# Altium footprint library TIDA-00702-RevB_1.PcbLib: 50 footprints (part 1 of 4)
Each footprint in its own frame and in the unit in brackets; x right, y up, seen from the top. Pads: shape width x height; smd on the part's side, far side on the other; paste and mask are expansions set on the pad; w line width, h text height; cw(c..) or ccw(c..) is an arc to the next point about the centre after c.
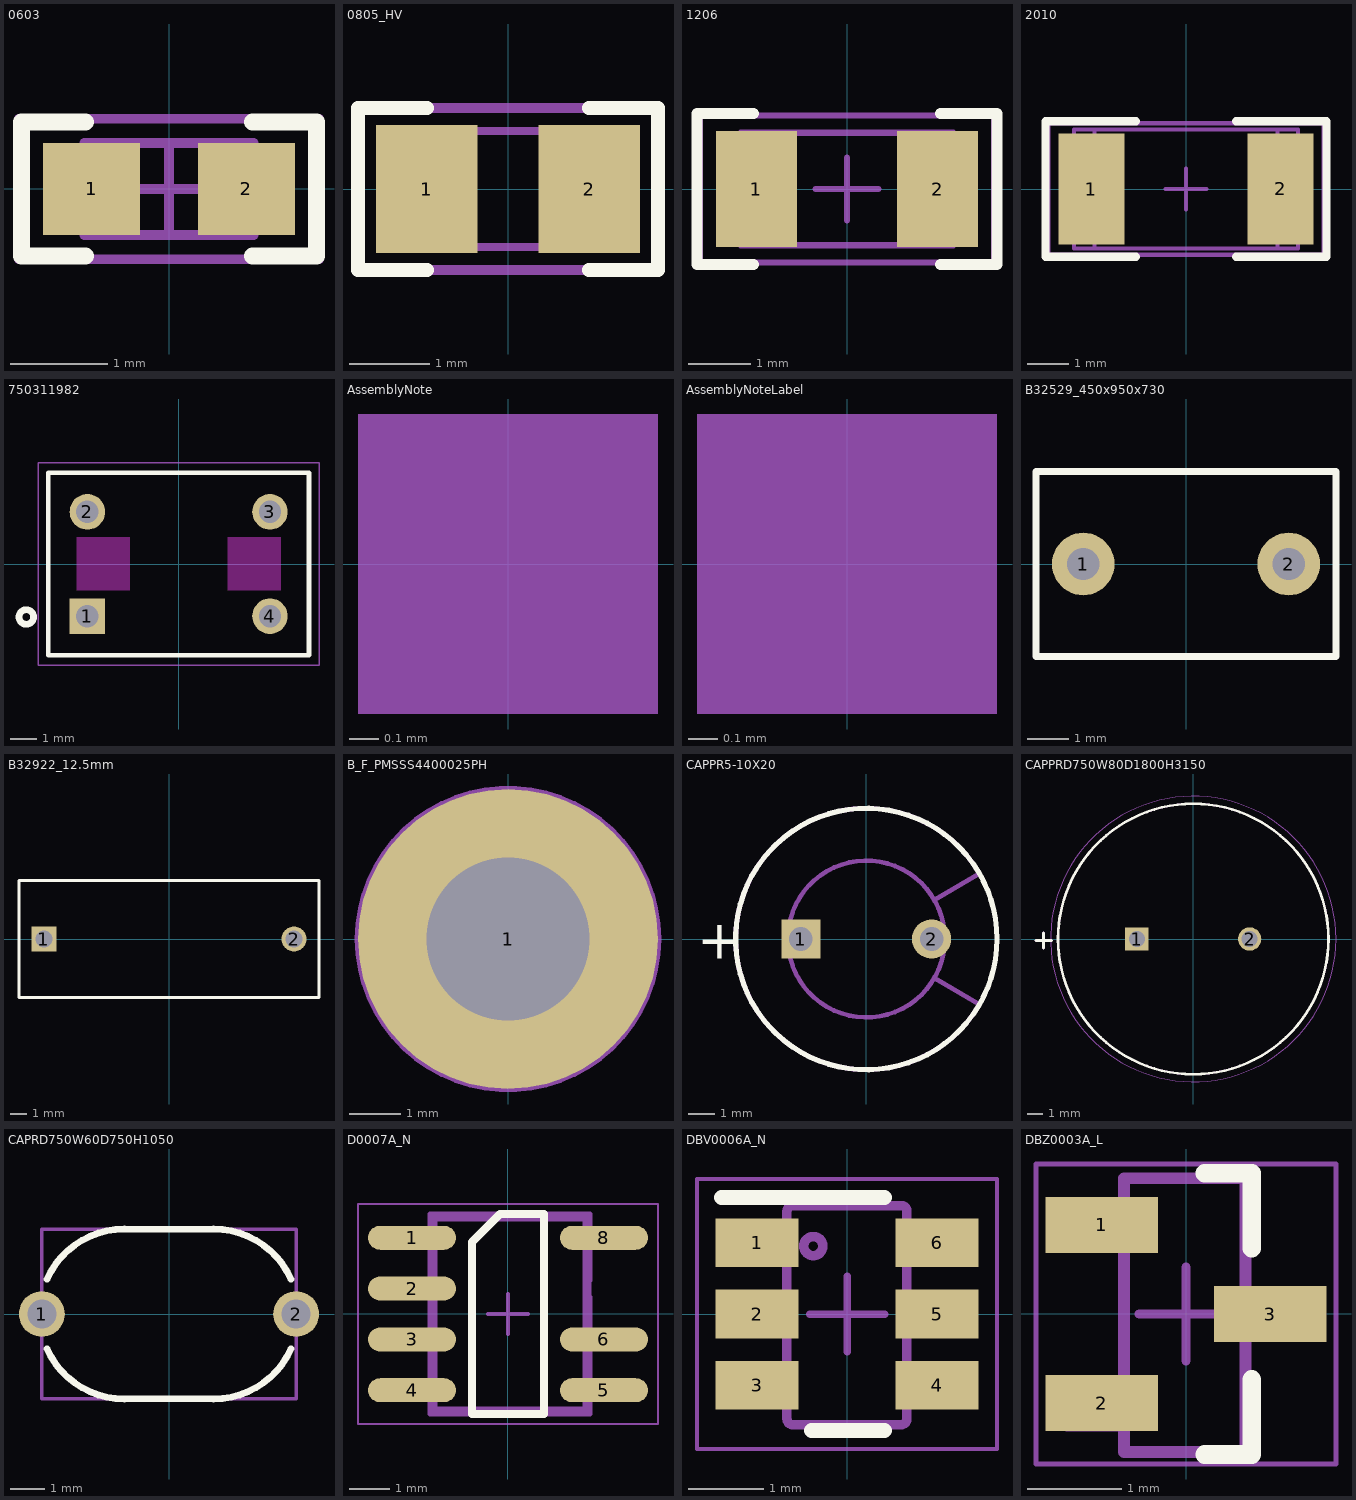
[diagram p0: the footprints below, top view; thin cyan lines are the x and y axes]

## 0603 [mm] "0603 from SM-752 data"
height 0.85
pads (2):
  rect 1x0.95 smd: 1(-0.8,0) 2(0.8,0)
Top Overlay:
  lines w0.178: -0.864,-0.691 -1.524,-0.691 -1.524,0.693 -0.864,0.693 ; 0.864,-0.691 1.524,-0.691 1.524,0.693 0.864,0.693
Mechanical 5:
  lines w0.1: -1.55,-0.725 1.55,-0.725 1.55,0.725 -1.55,0.725 -1.55,-0.725
  text ".Designator" at 1.162,0.431 h0.89
Mechanical 13:
  lines w0.1: -0.55,-0.475 -0.55,0.475 ; 0.55,-0.475 0.55,0.475 ; -0.875,-0.475 -0.875,0.475 0.875,0.475 0.875,-0.475 -0.875,-0.475
Mechanical 15:
  lines w0.1: -0.475,0 0.475,0 ; 0,-0.475 0,0.475 ; -1.55,-0.725 -1.55,0.725 1.55,0.725 1.55,-0.725 -1.55,-0.725
3D body: height 0.85, standoff 0, extent 0.551,-0.474 0.874,0.474
3D body: height 0.85, standoff 0, extent -0.549,-0.474 0.549,0.474
3D body: height 0.85, standoff 0, extent -0.874,-0.474 -0.551,0.474

## 0805_HV [mil] "0805 with 30mil clearance between pads"
height 43.31
pads (2):
  rect 50x63 smd: 1(-40,0) 2(40,0)
Top Overlay:
  lines w7: -40,-40 -74,-40 -74,0 -74,40 -40,40 ; 40,-40 74,-40 74,0 74,40 40,40
Mechanical 5:
  lines w5: -74,-40 -74,40 74,40 74,-40 -74,-40
  text ".Designator" at 37,22 h35
Mechanical 13:
  lines w3.94: -25.59,-28.54 -25.59,28.54 ; 25.59,-28.54 25.59,28.54 ; -43.31,-28.54 43.31,-28.54 43.31,28.54 -43.31,28.54 -43.31,-28.54
3D body: height 43.31, standoff 0, extent -43.29,-28.52 -25.61,28.52
3D body: height 43.31, standoff 0, extent -25.57,-28.52 25.57,28.52
3D body: height 43.31, standoff 0, extent 25.61,-28.52 43.29,28.52

## 1206 [mm] "1206 from SM-752 data"
height 1.35
pads (2):
  rect 1.3x1.85 smd: 1(-1.45,0) 2(1.45,0)
Top Overlay:
  lines w0.178: -1.5,-1.21 -2.4,-1.21 -2.4,1.21 -1.5,1.21 ; 1.5,-1.21 2.4,-1.21 2.4,1.21 1.5,1.21
Mechanical 5:
  lines w0.1: -1.7,-0.9 1.7,-0.9 1.7,0.9 -1.7,0.9 -1.7,-0.9
  text ".Designator" at -1.475,-0.4 h0.89
Mechanical 13:
  lines w0.1: -1.2,-0.9 -1.2,0.9 ; 1.2,-0.9 1.2,0.9 ; -1.7,-0.9 1.7,-0.9 1.7,0.9 -1.7,0.9 -1.7,-0.9
Mechanical 15:
  lines w0.1: -0.5,0 0.5,0 ; 0,-0.5 0,0.5 ; -2.35,-1.175 2.35,-1.175 2.35,1.175 -2.35,1.175 -2.35,-1.175
3D body: height 1.35, standoff 0, extent -1.699,-0.899 -1.201,0.899
3D body: height 1.35, standoff 0, extent -1.199,-0.899 1.199,0.899
3D body: height 1.35, standoff 0, extent 1.201,-0.899 1.699,0.899

## 2010 [mm] "Chip Capacitor, Body 5.08x2.54mm, IPC Medium Density"
height 1.66
pads (2):
  rect 1.6x2.7 smd: 1(-2.3,0) 2(2.3,0)
Top Overlay:
  lines w0.2: -1.219,-1.65 -3.419,-1.65 -3.419,1.65 -1.219,1.65 ; 1.219,-1.65 3.419,-1.65 3.419,1.65 1.219,1.65
Mechanical 5:
  lines w0.1: -2.73,-1.45 -2.73,1.45 2.73,1.45 2.73,-1.45 -2.73,-1.45
  text ".Designator" at -0.787,0.737 h0.89
Mechanical 13:
  lines w0.1: -2.23,-1.45 -2.23,1.45 ; 2.23,-1.45 2.23,1.45 ; -2.73,-1.45 2.73,-1.45 2.73,1.45 -2.73,1.45 -2.73,-1.45
Mechanical 15:
  lines w0.1: -0.5,0 0.5,0 ; 0,-0.5 0,0.5 ; -3.35,-1.6 3.35,-1.6 3.35,1.6 -3.35,1.6 -3.35,-1.6
3D body: height 1.66, standoff 0, extent -2.729,-1.449 -2.231,1.449
3D body: height 1.66, standoff 0, extent -2.229,-1.449 2.229,1.449
3D body: height 1.66, standoff 0, extent 2.231,-1.449 2.729,1.449

## 750311982 [mm] "4 LEAD,TH"
height 6.8
pads (4):
  rect 1.362x1.362 / inner round 1.362 / far side rect 1.362x1.362 hole 0.854: 1(-3.5,-2)
  round 1.362 hole 0.854: 2(-3.5,2) 3(3.5,2) 4(3.5,-2)
Top Layer keep-out:
  rectangle: 1.874,-1.024 3.928,1.03
  rectangle: -3.926,-1.024 -1.872,1.03
Top Overlay:
  circle w0.254: c-5.842,-2.032 r0.279
  lines w0.178: -5,-3.5 -5,3.5 5,3.5 5,-3.5 -5,-3.5
  text ".Designator" at -5.597,-0.279 h0.89
Bottom Overlay:
  lines w0.178: -5,-3.5 -5,-2.5 ; -5,-1.5 -5,-0.5 ; -5,0.5 -5,1.5 ; -5,2.5 -5,3.5 ; -4.572,-3.5 -3.572,-3.5 ; -4.572,3.5 -3.572,3.5 ; -2.572,-3.5 -1.572,-3.5 ; -2.572,3.5 -1.572,3.5 ; -0.572,-3.5 0.428,-3.5 ; -0.572,3.5 0.428,3.5 ; 1.428,-3.5 2.428,-3.5 ; 1.428,3.5 2.428,3.5 ; 3.428,-3.5 4.428,-3.5 ; 3.428,3.5 4.428,3.5 ; 5,-3.5 5,-2.5 ; 5,-1.5 5,-0.5 ; 5,0.5 5,1.5 ; 5,2.5 5,3.5
Mechanical 5:
  lines w0.127: -5,-3.5 5,-3.5 5,3.5 -5,3.5 -5,-3.5
  text ".Designator" at 0.296,-0.737 h0.89
Mechanical 15:
  lines w0.05: -5.381,-3.881 -5.381,3.881 5.381,3.881 5.381,-3.881 -5.381,-3.881
Mechanical 17:
  text "LEAD LENGTH:3 +/- 0.5MM" at -10.795,1.651 h1.02
3D body: height 6.8, standoff 0, extent -5,-3.5 5,3.5

## AssemblyNote [mm] "Assembly Note"
Mechanical 5:
  rectangle: -0.508,-0.508 0.508,0.508
  text ".Designator" at -4.191,-0.508 h0.89
  text ".Comment" at 1.143,-0.508 h0.89

## AssemblyNoteLabel [mm] "Assembly Note for PCB Labels"
Mechanical 5:
  rectangle: -0.508,-0.508 0.508,0.508
  text ".Designator" at -4.191,-0.508 h0.89
  text "Install label in silkscreened box after final wash.  Text shall be 8 pt font.  Text shall be per the Label Table in the PDF schematic." at 1.143,-0.508 h0.89

## B32529_450x950x730 [mil] "EPCOS"
height 374.02
pads (2):
  round 60 hole 31: 1(-98.43,0) 2(98.43,0)
Top Overlay:
  lines w7: -143.7,-88.58 -143.7,88.58 143.7,88.58 143.7,-88.58 -143.7,-88.58
Mechanical 5:
  lines w3.94: -143.7,-88.58 143.7,-88.58 143.7,88.58 -143.7,88.58 -143.7,-88.58
  text ".Designator" at -70.87,-19.68 h35
3D body: height 374.02, standoff 0, extent -143.7,-88.58 143.7,88.58
3D body: height 0, standoff -78.74, extent 88.66,-9.82 108.27,9.82
3D body: height 0, standoff -78.74, extent -108.19,-9.82 -88.58,9.82

## B32922_12.5mm [mm] "Epcos film capacitors, 15mm spacing"
height 12.5
pads (2):
  rect 1.5x1.5 hole 1: 1(-7.5,0)
  round 1.5 hole 1: 2(7.5,0)
Top Overlay:
  lines w0.178: -9,-3.5 -9,0 -9,3.5 0,3.5 9,3.5 9,0 9,-3.5 0,-3.5 -9,-3.5
Mechanical 5:
  lines w0.127: -9,-3.5 0,-3.5 9,-3.5 9,0 9,3.5 0,3.5 -9,3.5 -9,0 -9,-3.5
  text ".Designator" at 0.419,-0.67 h0.89
3D body: height 12.5, standoff 0, extent -8.999,-3.499 8.999,3.499

## B_F_PMSSS4400025PH [mil] "MACHINE SCREW PAN PHILLIPS 4-40"
height 82.68
pads (1):
  round 230 hole 125: 1(0,0)
Mechanical 5:
  circle w5: c0,0 r115
  text ".Designator" at -33,-16 h35
3D body: height 79.21, standoff -248.03, extent -109.49,-109.49 109.51,109.51

## CAPPR5-10X20 [mm] "Capacitor, Electrolytic, Radial; Body 10 x 20 mm (Dia.xH typ); Pin Spacing 5 mm (typ)"
height 22
pads (2):
  rect 1.5x1.5 hole 0.9: 1(-2.5,0)
  round 1.5 hole 0.9: 2(2.5,0)
Top Overlay:
  circle w0.2: c0,0 r5
  text "+" at -6.475,-0.75 h1.5
Mechanical 5:
  text ".Designator" at -0.127,-0.813 h0.89
Mechanical 13:
  circle w0.178: c0,0 r3
  circle w0.178: c-2.5,0 r0.3
  circle w0.178: c2.5,0 r0.3
  lines w0.178: 2.623,-1.5 4.33,-2.5 cw(c0,0) 4.33,2.5 ; 2.623,1.5 4.33,2.5
3D body: height 22, standoff 0, extent 2.597,-2.506 5.011,2.506
3D body: height 22, standoff 0, extent -5.01,-5.01 4.339,5.01
3D body: height 22, standoff 0, extent -3.009,-3.009 3.009,3.009
3D body: height 1, standoff -2.54, extent -2.805,-0.305 -2.195,0.305
3D body: height 1, standoff -2.54, extent 2.195,-0.305 2.805,0.305

## CAPPRD750W80D1800H3150 [mm] "CAPACITOR, POLARIZED, 0.8MM LEAD DIA, PITCH 7.5MM"
height 33
pads (2):
  rect 1.554x1.554 / inner round 1.554 / far side rect 1.554x1.554 hole 1.054: 1(-3.75,0)
  round 1.554 hole 1.054: 2(3.75,0)
Top Overlay:
  circle w0.178: c0,0 r9
  lines w0.2: -10.465,-0.102 -9.449,-0.102 ; -9.957,-0.61 -9.957,0.406
Mechanical 5:
  circle w0.127: c0,0 r9
  lines w0.2: -10.465,-0.102 -9.449,-0.102 ; -9.957,-0.61 -9.957,0.406
  text ".Designator" at 0.305,0.025 h0.89
Mechanical 15:
  circle w0.05: c0,0 r9.5
3D body: height 33, standoff 0, extent -8.929,-8.982 9,8.982

## CAPRD750W60D750H1050 [mm] "Vishay BC Components"
height 10.5
pads (2):
  round 1.35 hole 0.85: 1(-3.75,0) 2(3.75,0)
Top Overlay:
  lines w0.2: -3.6,-1.025 ccw(c-1.316,-0.008) -1.316,-2.508 ; -3.6,1.025 cw(c-1.316,0.008) -1.316,2.508 ; -1.5,-2.5 1.5,-2.5 ; -1.5,2.5 1.5,2.5 ; 1.316,-2.508 ccw(c1.316,-0.008) 3.6,-1.025 ; 1.316,2.508 cw(c1.316,0.008) 3.6,1.025
Mechanical 5:
  lines w0.1: -3.75,-2.5 3.75,-2.5 3.75,2.5 -3.75,2.5 -3.75,-2.5
  text ".Designator" at -0.94,1.245 h0.89
3D body: height 6, standoff -2, extent 3.453,-0.299 4.05,0.3
3D body: height 6, standoff -2, extent -4.047,-0.299 -3.45,0.3
3D body: height 10.49, standoff 3.01, extent -3.72,-2.5 3.75,2.5

## D0007A_N [mm] "SOIC, 7-Leads, Body 4.9x3.9mm, Pitch 1.27mm, IPC Medium Density"
height 1.75
pads (7):
  oval 2.2x0.6 smd: 1(-2.4,1.905) 2(-2.4,0.635) 3(-2.4,-0.635) 4(-2.4,-1.905) 5(2.4,-1.905) 6(2.4,-0.635) 8(2.4,1.905)
Top Overlay:
  lines w0.2: -0.9,-2.5 -0.9,1.8 -0.2,2.5 0.9,2.5 0.9,-2.5 -0.9,-2.5
Mechanical 5:
  lines w0.127: -1.95,-2.11 -1.95,-2.5 ; -1.95,-1.7 -1.95,-0.84 ; -1.95,-0.43 -1.95,0.43 ; -1.95,0.84 -1.95,1.7 ; -1.95,2.11 -1.95,2.5 ; 2.05,-2.11 2.05,-2.5 ; 2.05,-1.7 2.05,-0.84 ; 2.05,-0.43 2.05,0.43 2.03,0.43 2.03,0.84 2.05,0.84 2.05,1.7 ; 2.05,2.11 2.05,2.5 ; -2.325,-2.11 -2.325,-1.7 ; -2.325,-2.11 -2.045,-2.11 -1.931,-2.11 -1.931,-1.7 -2.045,-1.7 -2.325,-1.7 ; -2.325,-2.11 -2.39,-2.11 -2.95,-2.11 -2.95,-1.7 -2.39,-1.7 -2.325,-1.7 ; -2.325,-0.84 -2.325,-0.43 ; -2.325,-0.84 -2.045,-0.84 -1.931,-0.84 -1.931,-0.43 -2.045,-0.43 -2.325,-0.43 ; -2.325,-0.84 -2.39,-0.84 -2.95,-0.84 -2.95,-0.43 -2.39,-0.43 -2.325,-0.43 ; -2.325,0.43 -2.045,0.43 -1.931,0.43 -1.931,0.84 -2.045,0.84 -2.325,0.84 ; -2.325,0.43 -2.39,0.43 -2.95,0.43 -2.95,0.84 -2.39,0.84 -2.325,0.84 ; -2.325,0.43 -2.325,0.84 ; -2.325,1.7 -2.045,1.7 -1.931,1.7 -1.931,2.11 -2.045,2.11 -2.325,2.11 ; -2.325,1.7 -2.325,2.11 ; -2.325,1.7 -2.39,1.7 -2.95,1.7 -2.95,2.11 -2.39,2.11 -2.325,2.11 ; -1.95,-2.5 2.05,-2.5 ; -1.95,-2.5 -1.822,-2.372 ; -1.95,2.5 -1.822,2.372 ; -1.95,2.5 2.05,2.5 ; -1.822,-2.372 -1.822,2.372 ; -1.822,-2.372 1.922,-2.372 ; -1.822,2.372 1.922,2.372 ; 1.922,-2.372 1.922,2.372 ; 1.922,-2.372 2.05,-2.5 ; 1.922,2.372 2.05,2.5 ; 2.425,-2.11 2.49,-2.11 3.05,-2.11 3.05,-1.7 2.49,-1.7 2.425,-1.7 ; 2.425,-2.11 2.145,-2.11 2.031,-2.11 2.031,-1.7 2.145,-1.7 2.425,-1.7 ; 2.425,-2.11 2.425,-1.7 ; 2.425,-0.84 2.49,-0.84 3.05,-0.84 3.05,-0.43 2.49,-0.43 2.425,-0.43 ; 2.425,-0.84 2.145,-0.84 2.031,-0.84 2.032,-0.43 2.145,-0.43 2.425,-0.43 ; 2.425,-0.84 2.425,-0.43 ; 2.425,1.7 2.49,1.7 3.05,1.7 3.05,2.11 2.49,2.11 2.425,2.11 ; 2.425,1.7 2.145,1.7 2.031,1.7 2.031,2.11 2.145,2.11 2.425,2.11 ; 2.425,1.7 2.425,2.11
  text ".Designator" at -0.572,0.989 h0.89
Mechanical 15:
  lines w0.05: -3.75,-2.75 3.75,-2.75 3.75,2.75 -3.75,2.75 -3.75,-2.75
  lines w0.1: -0.5,0 0.5,0 ; 0,-0.5 0,0.5
3D body: height 1.54, standoff -0.01, extent -3,-2.5 3,2.5

## DBV0006A_N [mm] "SOT23, 6-Leads, Body 2.9x1.6mm, Pitch 0.95mm, Lead Span 2.8mm, IPC Medium Density"
height 1.45
pads (6):
  rect 1.1x0.65 smd: 1(-1.2,0.95) 2(-1.2,0) 3(-1.2,-0.95) 4(1.2,-0.95) 5(1.2,0) 6(1.2,0.95)
Top Overlay:
  lines w0.2: -1.675,1.55 0.5,1.55 ; -0.475,-1.55 0.5,-1.55
Mechanical 5:
  lines w0.127: 0.724,-1.475 ccw(c0.723,-1.399) 0.8,-1.399 0.799,1.37 ccw(c0.723,1.37) 0.724,1.446 ; 0.723,-1.475 0.724,-1.475 ; 0.723,-1.475 -0.725,-1.475 -0.725,-1.475 cw(c-0.724,-1.399) -0.801,-1.399 -0.801,1.37 cw(c-0.724,1.37) -0.725,1.446 -0.725,1.446 0.723,1.446 ; 0.723,1.446 0.724,1.446 ; -1.423,-1.154 -1.206,-1.154 -1.113,-1.154 -1.081,-1.154 -0.828,-1.154 -0.801,-1.154 -0.801,-0.78 -0.828,-0.78 -1.081,-0.78 -1.113,-0.78 -1.206,-0.78 -1.423,-0.78 -1.423,-1.154 ; -1.423,-0.202 -1.206,-0.202 -1.113,-0.202 -1.081,-0.202 -0.828,-0.202 -0.801,-0.202 -0.801,0.173 -0.828,0.173 -1.081,0.173 -1.113,0.173 -1.206,0.173 -1.423,0.173 -1.423,-0.202 ; -1.423,0.751 -1.206,0.751 -1.113,0.751 -1.081,0.751 -0.828,0.751 -0.801,0.751 -0.801,1.125 -0.828,1.125 -1.081,1.125 -1.113,1.125 -1.206,1.125 -1.423,1.125 -1.423,0.751 ; -0.577,0.906 cw(c-0.45,0.906) -0.323,0.906 cw(c-0.45,0.906) -0.577,0.906 ; 0.799,-1.154 0.827,-1.154 1.08,-1.154 1.112,-1.154 1.205,-1.154 1.422,-1.154 1.422,-0.78 1.205,-0.78 1.112,-0.78 1.08,-0.78 0.827,-0.78 0.799,-0.78 0.799,-1.154 ; 0.799,-0.202 0.827,-0.202 1.08,-0.202 1.112,-0.202 1.205,-0.202 1.422,-0.202 1.422,0.173 1.205,0.173 1.112,0.173 1.08,0.173 0.827,0.173 0.799,0.173 0.799,-0.202 ; 0.799,0.751 0.827,0.751 1.08,0.751 1.112,0.751 1.205,0.751 1.422,0.751 1.422,1.125 1.205,1.125 1.112,1.125 1.08,1.125 0.827,1.125 0.799,1.125 0.799,0.751
  text ".Designator" at -0.356,0.457 h0.89
Mechanical 15:
  lines w0.05: -2,-1.8 -2,1.8 2,1.8 2,-1.8 -2,-1.8
  lines w0.1: -0.5,0 0.5,0 ; 0,-0.5 0,0.5
3D body: height 1.11, standoff -0.01, extent -1.422,-1.461 1.422,1.46

## DBZ0003A_L [mm] "SOT23, 3-Leads, Body 2.9x1.3mm, Pitch 0.95mm, Lead Span 2.4mm, IPC High Density"
height 1.12
pads (3):
  rect 1.2x0.6 smd: 1(-0.9,0.95) 2(-0.9,-0.95) 3(0.9,0)
Top Overlay:
  lines w0.2: 0.2,-1.5 0.7,-1.5 0.7,-0.7 ; 0.2,1.5 0.7,1.5 0.7,0.7
Mechanical 5:
  lines w0.127: -1.27,-1.187 -1.27,-0.743 -1.063,-0.743 -1.005,-0.743 -0.814,-0.743 -0.66,-0.743 -0.66,-1.187 -0.814,-1.187 -1.005,-1.187 -1.063,-1.187 -1.27,-1.187 ; -1.27,0.718 -1.27,1.162 -1.063,1.162 -1.005,1.162 -0.814,1.162 -0.66,1.162 -0.66,0.718 -0.814,0.718 -1.005,0.718 -1.063,0.718 -1.27,0.718 ; -0.66,-1.473 -0.66,1.448 0.635,1.448 0.635,-1.473 -0.66,-1.473 ; 0.635,-0.235 0.789,-0.235 0.98,-0.235 1.037,-0.235 1.245,-0.235 1.245,0.21 1.037,0.21 0.98,0.21 0.789,0.21 0.635,0.21 0.635,-0.235
  text ".Designator" at 0.381,-1.067 h0.89
Mechanical 15:
  lines w0.05: -1.6,-1.6 1.6,-1.6 1.6,1.6 -1.6,1.6 -1.6,-1.6
  lines w0.1: -0.5,0 0.5,0 ; 0,-0.5 0,0.5
3D body: height 0.96, standoff -0.02, extent -1.257,-1.461 1.257,1.46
